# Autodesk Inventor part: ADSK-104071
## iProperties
Shininess: 0.0
Created: 2000-10
Part Number: ADSK-104071
Document SubType Name: Modeling
Designer: gao
Stock Number: ADSK-104071
Density: 1 g/cm^3
Density: 0.0
Volumn: 0.0
Area: 0.0
PropertySet Name: Model Information
Control State: 0
Master: False
Checked Out: False
Author: gao
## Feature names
1. Hole11
2. Hole12
